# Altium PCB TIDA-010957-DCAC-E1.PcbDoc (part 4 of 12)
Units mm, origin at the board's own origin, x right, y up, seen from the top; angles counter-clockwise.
Board outline 300 x 300 mm, 4 copper layers (Top Layer, Layer 1, Layer 2, Bottom Layer), stack 1.787 mm thick; 1159 components, 619 nets, 3431 pads, 2942 vias.
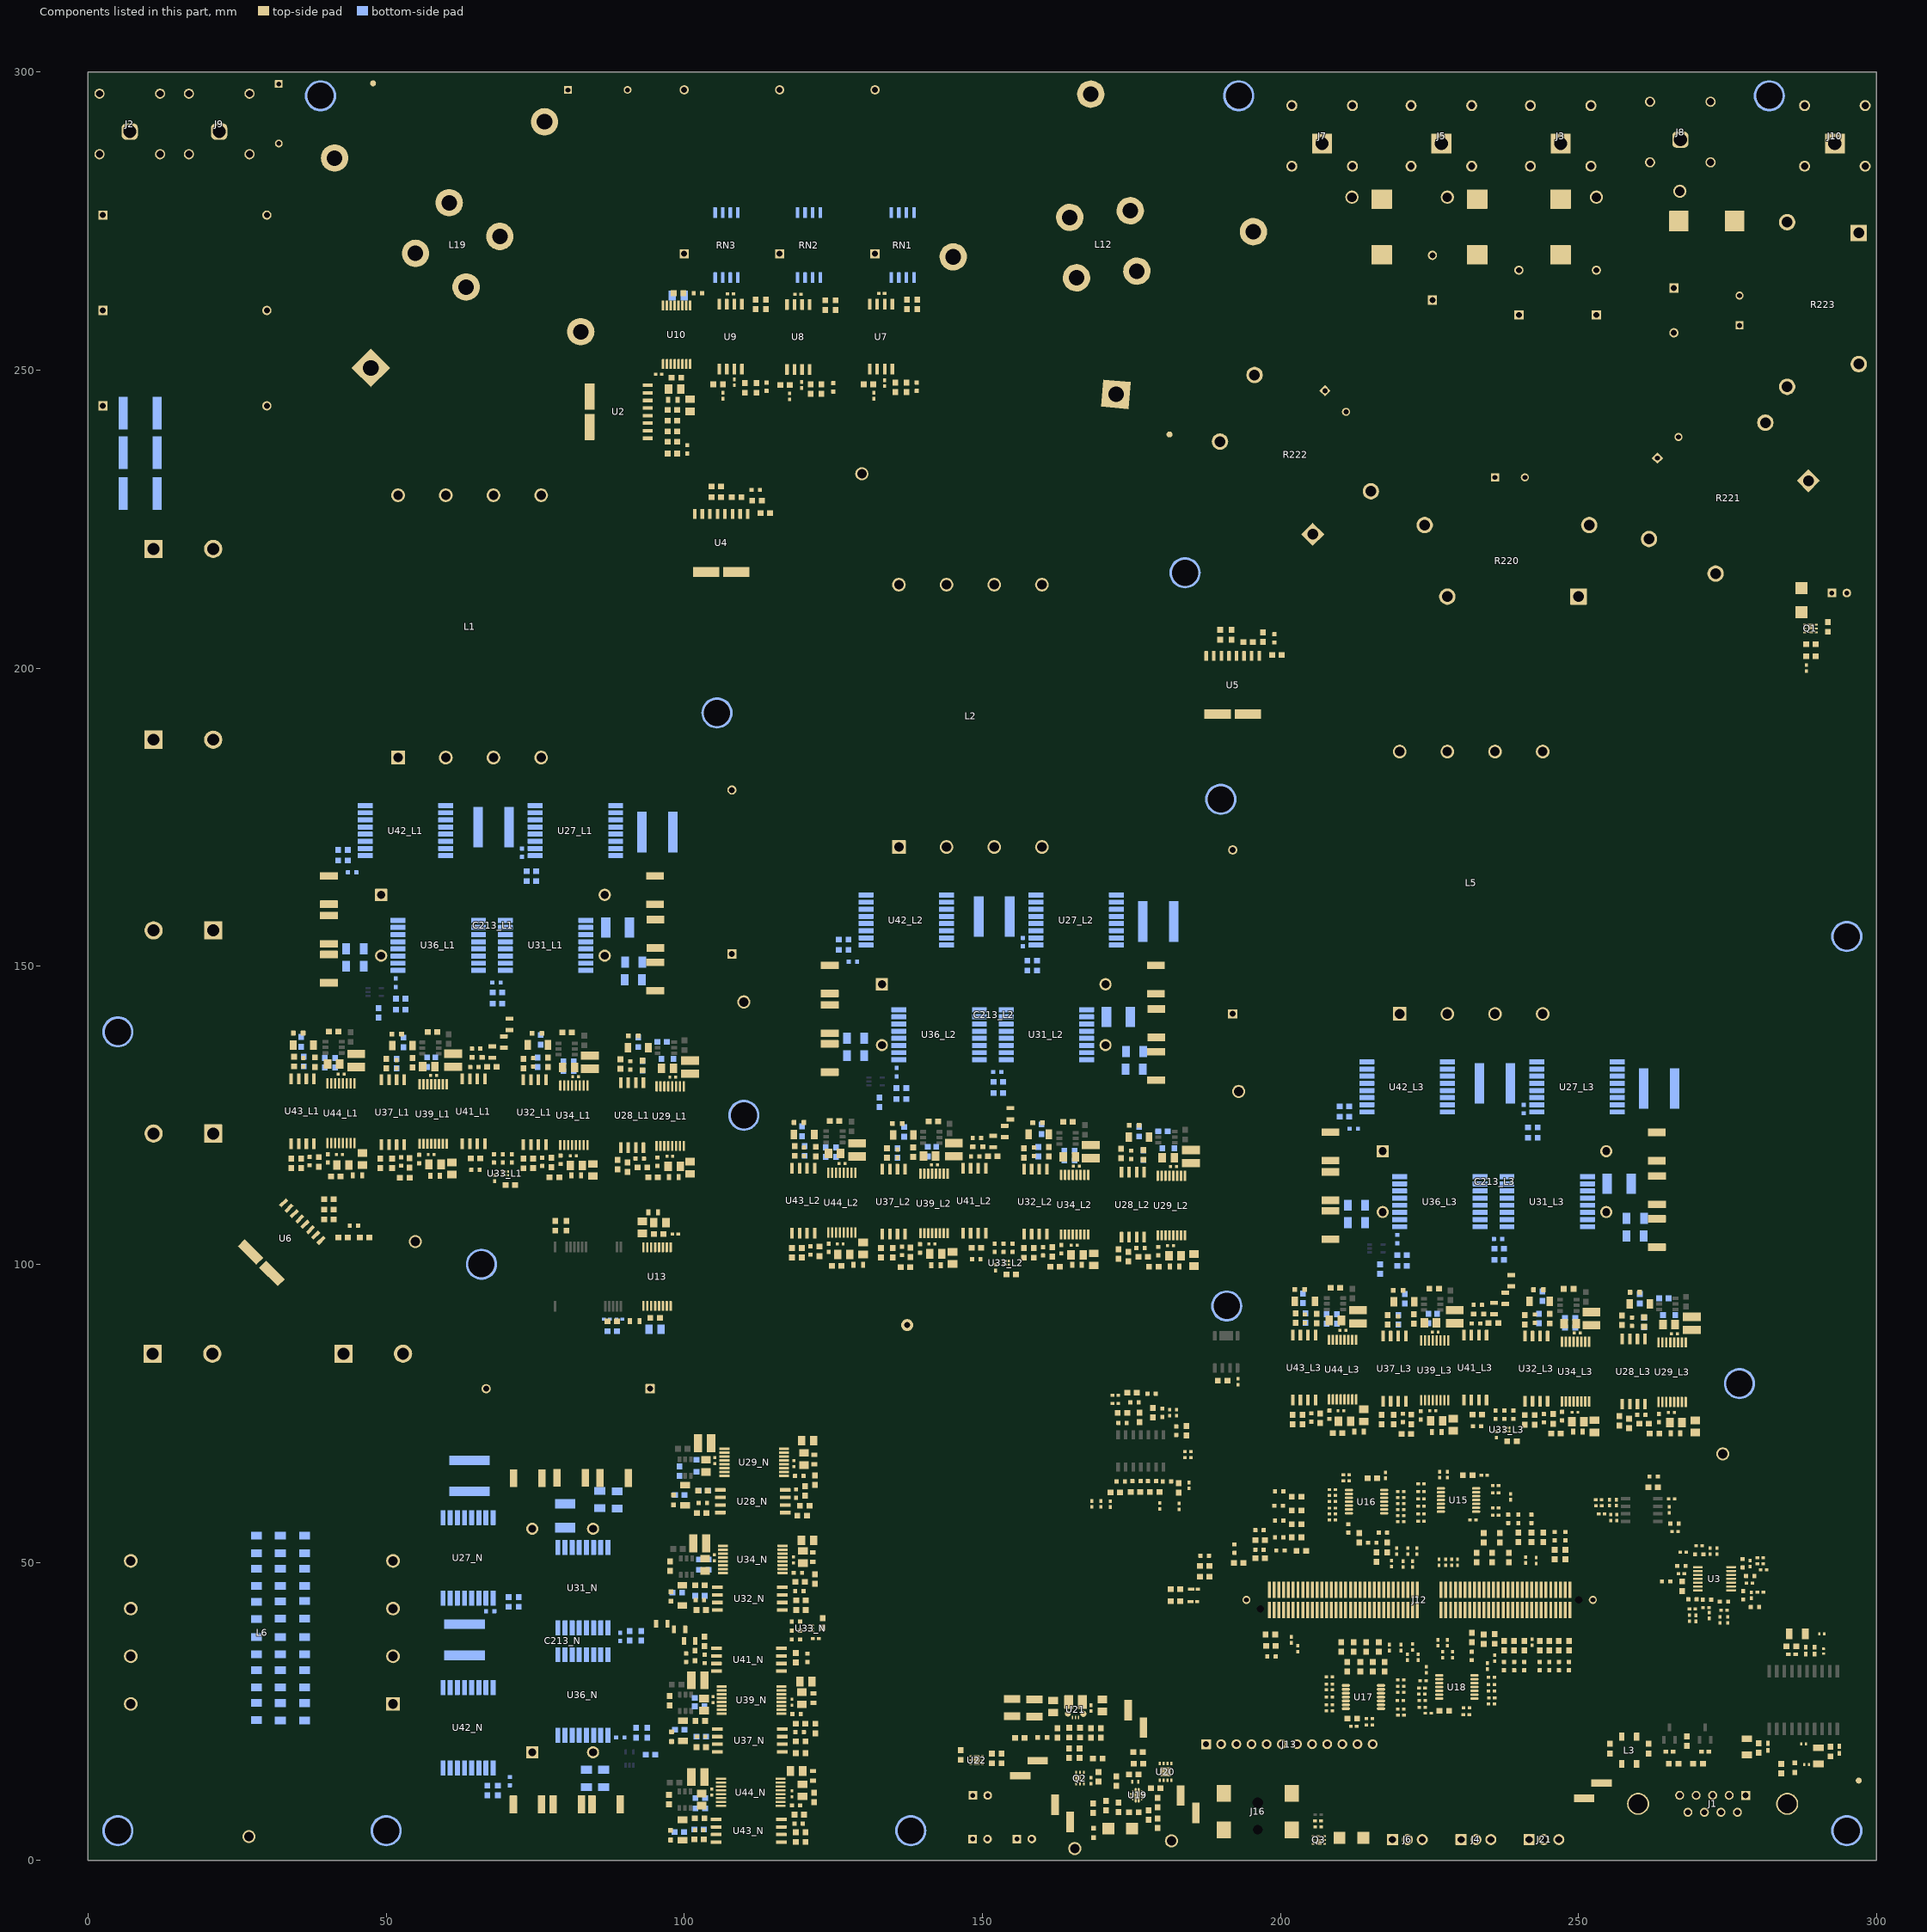
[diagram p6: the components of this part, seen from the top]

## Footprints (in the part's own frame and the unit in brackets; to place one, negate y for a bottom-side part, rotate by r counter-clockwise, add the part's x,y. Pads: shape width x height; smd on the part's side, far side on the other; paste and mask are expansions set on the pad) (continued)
DHA0016A-MFG [mm]
  rrect24% 1.65x0.41 smd paste+0 mask+0: 1(-4.925,2.275) 2(-4.925,1.625) 3(-4.925,0.975) 4(-4.925,0.325) 5(-4.925,-0.325) 6(-4.925,-0.975) 7(-4.925,-1.625) 8(-4.925,-2.275) 9(4.925,-2.275) 10(4.925,-1.625) 11(4.925,-0.975) 12(4.925,-0.325) 13(4.925,0.325) 14(4.925,0.975) 15(4.925,1.625) 16(4.925,2.275)
  silkscreen extent -6.42,-2.98 3.5,2.98, body extent -5.85,-3.22 5.85,3.22, height 0.25
DQK0006C [mm] "WSON"
  rrect12% 0.9x0.86 on Top Paste: 0(0,0.325)
  rrect34% 0.7x0.29 on Top Paste: 0(0.095,-0.65)
  rrect33% 0.45x0.3 smd: 1(-0.975,0.65) 2(-0.975,0) 3(-0.975,-0.65) 4(0.975,-0.65) 5(0.975,0) 6(0.975,0.65)
  rrect33% 0.75x0.3 smd paste-0.15: 7(0.095,-0.65)
  rrect11% 1x0.95 smd paste-0.5: 8(0,0.325)
  silkscreen extent -1.15,-1.15 1.15,1.15, body extent -1,-1 1,1, height 0.82
DRB0008A [mm] "VSON-8"
  rrect32% 0.6x0.31 smd: 1(-1.4,0.975) 2(-1.4,0.325) 3(-1.4,-0.325) 4(-1.4,-0.975) 5(1.4,-0.975) 6(1.4,-0.325) 7(1.4,0.325) 8(1.4,0.975)
  rrect7% 1.5x1.75 smd paste-0.75: 9(0,0)
  Top Layer region: -0.7,-0.875 -0.49,-0.875 -0.471,-0.879 -0.455,-0.89 -0.444,-0.906 -0.44,-0.925 -0.44,-0.925 -0.44,-1.65 -0.436,-1.669 -0.425,-1.685 -0.409,-1.696 -0.39,-1.7 -0.39,-1.7 -0.26,-1.7 -0.241,-1.696 -0.225,-1.685 -0.214,-1.669 -0.21,-1.65 -0.21,-1.65 -0.21,-0.925 -0.206,-0.906 -0.195,-0.89 -0.179,-0.879 -0.16,-0.875 -0.16,-0.875 0.16,-0.875 0.179,-0.879 0.195,-0.89 0.206,-0.906 0.21,-0.925 0.21,-0.925 0.21,-1.65 0.21,-1.65 0.214,-1.669 0.225,-1.685 0.241,-1.696 0.26,-1.7 0.26,-1.7 0.39,-1.7 0.409,-1.696 0.425,-1.685 0.436,-1.669 0.44,-1.65 0.44,-1.65 0.44,-0.925 0.444,-0.906 0.455,-0.89 0.471,-0.879 0.49,-0.875 0.49,-0.875 0.7,-0.875 0.719,-0.871 0.735,-0.86 0.746,-0.844 0.75,-0.825 0.75,-0.825 0.75,0.825 0.746,0.844 0.735,0.86 0.719,0.871 0.7,0.875 0.7,0.875 0.49,0.875 0.471,0.879 0.455,0.89 0.444,0.906 0.44,0.925 0.44,0.925 0.44,1.65 0.436,1.669 0.425,1.685 0.409,1.696 0.39,1.7 0.39,1.7 0.26,1.7 0.241,1.696 0.225,1.685 0.214,1.669 0.21,1.65 0.21,1.65 0.21,1.65 0.21,0.925 0.206,0.906 0.195,0.89 0.179,0.879 0.16,0.875 0.16,0.875 -0.16,0.875 -0.179,0.879 -0.195,0.89 -0.206,0.906 -0.21,0.925 -0.21,0.925 -0.21,1.65 -0.214,1.669 -0.225,1.685 -0.241,1.696 -0.26,1.7 -0.26,1.7 -0.39,1.7 -0.409,1.696 -0.425,1.685 -0.436,1.669 -0.44,1.65 -0.44,1.65 -0.44,0.925 -0.444,0.906 -0.455,0.89 -0.471,0.879 -0.49,0.875 -0.49,0.875 -0.7,0.875 -0.719,0.871 -0.735,0.86 -0.746,0.844 -0.75,0.825 -0.75,0.825 -0.75,-0.825 -0.746,-0.844 -0.735,-0.86 -0.719,-0.871 -0.7,-0.875
  silkscreen extent -1.73,-1.73 1.73,1.73, body extent -1.5,-1.5 1.5,1.5, height 0.77
DRV0006A [mm] "SON, 6-Leads, Body 2x2mm, Pitch 0.65mm, Thermal Pad 1.6x1mm, TI Recommended"
  rrect33% 0.45x0.3 smd: 1(-0.975,0.65) 2(-0.975,0) 3(-0.975,-0.65) 4(0.975,-0.65) 5(0.975,0) 6(0.975,0.65)
  rrect14% 1x0.7 on Top Paste: 7(0,-0.45) 7(0,0.45)
  rrect10% 1x1.6 smd paste-0.5: 7(0,0)
  silkscreen extent -1.05,-1.2 1.05,1.2, body extent -1.05,-1.05 1.05,1.05, height 0.81
DRY0006A [mm] "USON-6"
  rrect67% 0.45x0.3 smd paste-0.05 mask-0.05: 1(-0.275,0.5)
  rrect67% 0.4x0.3 smd paste-0.05 mask-0.05: 2(-0.3,0) 3(-0.3,-0.5) 4(0.3,-0.5) 5(0.3,0) 6(0.3,0.5)
  body extent -0.5,-0.72 0.5,0.72, height 0.58
DVG0010A-MFG [mm]
  rrect6% 1.65x4.41 smd paste+0 mask+0: 1(-4.875,2.54) 2(-4.875,-2.54)
  rrect17% 1.65x0.6 smd paste+0 mask+0: 3(4.875,-4.445) 4(4.875,-3.175) 5(4.875,-1.905) 6(4.875,-0.635) 7(4.875,0.635) 8(4.875,1.905) 9(4.875,3.175) 10(4.875,4.445)
  silkscreen extent -6.37,-5.25 3.67,5.25, body extent -5.15,-5.15 5.15,5.15, height 2.65
DWV0008A [mm] "SOIC, 8-Leads, Body 5.95x7.6mm (max), Pitch 1.27mm"
  rrect17% 1.8x0.6 smd: 1(-5.45,1.905) 2(-5.45,0.635) 3(-5.45,-0.635) 4(-5.45,-1.905) 5(5.45,-1.905) 6(5.45,-0.635) 7(5.45,0.635) 8(5.45,1.905)
  silkscreen extent -6.25,-2.95 2.98,2.95, body extent -5.77,-2.92 5.77,2.93, height 2.67
DWV0008A-MFG [mm]
  rrect17% 1.8x0.6 smd paste+0 mask+0: 1(-5.45,1.905) 2(-5.45,0.635) 3(-5.45,-0.635) 4(-5.45,-1.905) 5(5.45,-1.905) 6(5.45,-0.635) 7(5.45,0.635) 8(5.45,1.905)
  silkscreen extent -7.1,-2.98 3.8,2.98, body extent -5.75,-2.93 5.75,2.93, height 2.8
DWX0016A-MFG [mm]
  rrect24% 1.7x0.41 smd paste+0 mask+0: 1(-5,2.275) 2(-5,1.625) 3(-5,0.975) 4(-5,0.325) 5(-5,-0.325) 6(-5,-0.975) 7(-5,-1.625) 8(-5,-2.275) 9(5,-2.275) 10(5,-1.625) 11(5,-0.975) 12(5,-0.325) 13(5,0.325) 14(5,0.975) 15(5,1.625) 16(5,2.275)
  silkscreen extent -6.52,-2.98 3.8,2.98, body extent -5.16,-2.93 5.16,2.93, height 2.6
FCC_disclaimer [mm]
Fiducial10-20 [mm]
  round 1 smd mask+0.5: 1(0,0)
  Top Layer keep-out circle w1.178: c0,0 r0.5
FM_630x1120 [mm] "PANASONIC"
  rect 1.45x1.45 hole 0.787: 1(-1.25,0)
  round 1.45 hole 0.787: 2(1.25,0)
  silkscreen extent -3.4,-3.4 3.4,3.4, body extent -3.37,-3.39 3.4,3.39, height 12.71
FP-0022111031_HDR3-MFG [mm]
  rrect5% 1.85x1.85 hole 1.2 paste-2539.97 mask+0: 1(2.5,0.3)
  round 1.85 hole 1.2 paste-2539.97 mask+0: 2(0,0.3) 3(-2.5,0.3)
  silkscreen extent -4.1,-3.1 4.7,3.1, body extent -4.2,-3.2 4.2,3.2, height 0.25
FP-9774030960R_SPACER-MFG#1 [mm] "Recommended Land Pattern"
  round 5.245 smd paste-1000 mask-1000: 1(0,0)
  round 4.4 hole 4.4 unplated paste-2539.97 mask+0: ""(0,0)
  Top Layer circle w1.5: c0,0 r2.95
  silkscreen extent -4.08,-4.07 4.07,4.07, body extent -3,-3 2.99,3, height 3.1
FP-9774030960R_SPACER-MFG#2 [mm] "Recommended Land Pattern"
  round 5.245 smd paste-1000 mask-1000: 1(0,0)
  round 4.4 hole 4.4 unplated paste-2539.97 mask+0: ""(0,0)
  Top Layer lines w1.5: 2.615,1.365 cw(c0,0) -2.95,0 cw(c0,0) 2.615,1.365
  silkscreen extent -4.08,-4.07 4.07,4.07, body extent -3,-3 2.99,3, height 3.1
FP-ACT45B-101-2P-TL003_SMT_4MM5_3MM2-MFG [mm]
  rrect11% 1.35x0.9 smd paste+0 mask+0: 1(-2.275,1.25) 2(-2.275,-1.25) 3(2.275,-1.25) 4(2.275,1.25)
  silkscreen extent -3.62,-1.7 2.35,1.7, body extent -3.05,-1.8 3.05,1.8, height 0.25
FP-ALA7DA301CF550_RADIAL-MFG [mm] "Recommended Land Pattern"
  rrect3% 3.05x3.05 hole 2 paste-2539.97 mask+0: 1(-5,0)
  round 3.05 hole 2 paste-2539.97 mask+0: 2(5,0)
  silkscreen extent -15.5,-15.5 15.5,15.5, body extent -15.6,-15.6 15.6,15.6, height 0.25
FP-APG1608SURKC_T_0603-MFG [mm]
  rrect13% 0.8x0.8 smd paste-1000 mask+0: 1(-0.825,0) 2(0.825,0)
  silkscreen extent -1.92,-0.8 0.85,0.8, body extent -1.33,-0.55 1.33,0.55, height 0.25
FP-B32676G6126K000_RADIAL-MFG [mm] "Recommended Land Pattern"
  round 2.05 hole 1.35 paste-2539.97 mask+0: 1(-18.75,-5.1) 2(18.75,-5.1) 2(18.75,5.1)
  rrect5% 2.05x2.05 hole 1.35 paste-2539.97 mask+0: 1(-18.75,5.1)
  silkscreen extent -21,-14 21,14, body extent -21.1,-14.1 21.1,14.1, height 0.25
FP-B32774X1305K000_RADIAL-MFG [mm] "Recommended Land Pattern"
  rrect6% 1.55x1.55 hole 1 paste-2539.97 mask+0: 1(-13.75,0)
  round 1.55 hole 1 paste-2539.97 mask+0: 2(13.75,0)
  silkscreen extent -15.75,-9 15.75,9, body extent -15.85,-9.1 15.85,9.1, height 0.25
FP-B58043E5254M052_2220-MFG [mm]
  rrect7% 1.5x5.5 smd paste+0 mask+0: 1(-2.85,0) 2(2.85,0)
  silkscreen extent -1.73,-2.7 1.73,2.7, body extent -2.85,-2.5 2.85,2.5, height 1.6
"FP-B181178 V0 D6937_PTH8-MFG" [mm] "Recommended Land Pattern"
  rrect2% 4.6x4.6 hole 2.6 paste-2539.97 mask+0: 1(-4.3,24.9)
  round 4.6 hole 2.6 paste-2539.97 mask+0: 2(-6,4) 3(-24.9,-4.3) 4(-4,-6) 5(4.3,-24.9) 6(6,-4) 7(24.9,4.3) 8(4,6)
  silkscreen extent -28.37,-28.37 28.37,28.37, body extent -28.35,-28.35 28.35,28.35, height 0.25
"FP-B181179 V0 D6938_PTH8-MFG" [mm] "Recommended Land Pattern"
  rrect4% 2.3x2.3 hole 1.6 paste-2539.97 mask+0: 1(-22,12)
  round 2.3 hole 1.6 paste-2539.97 mask+0: 2(-22,4) 3(-22,-4) 4(-22,-12) 5(22,-12) 6(22,-4) 7(22,4) 8(22,12)
  silkscreen extent -29.17,-29.75 28.45,29.75, body extent -28.55,-29.85 28.55,29.85, height 0.25
FP-BLM15EX331SN1D_0402-MFG [mm]
  rrect25% 0.4x0.5 smd paste+0 mask+0: 1(-0.4,0) 2(0.4,0)
  silkscreen extent -0.53,-0.63 0.52,0.63, body extent -0.7,-0.38 0.7,0.38, height 0.25
FP-CGA3E2C0G1H331J080AA_0603-MFG [mm]
  rrect14% 0.7x0.7 smd paste+0 mask+0: 1(-0.7,0) 2(0.7,0)
  silkscreen extent -0.95,-0.72 0.95,0.72, body extent -1.15,-0.65 1.15,0.65, height 0.25
FP-FCR7350G_CONN_BANANA_JACK-MFG [mm]
  rrect3% 3.35x3.35 hole 2.2 paste-2539.97 mask+0: 1(11,0)
  round 1.85 hole 1.2 paste-2539.97 mask+0: 2(4.64,5.08) 3(14.8,5.08) 4(4.64,-5.08) 5(14.8,-5.08)
  silkscreen extent -1.83,-6.05 17.2,6.05, body extent -16.7,-6.15 16.7,6.15, height 0.25
FP-FCR7350N_CONN_BANANA_JACK-MFG [mm]
  rrect3% 3.35x3.35 hole 2.2 paste-2539.97 mask+0: 1(11,0)
  round 1.85 hole 1.2 paste-2539.97 mask+0: 2(4.64,5.08) 3(14.8,5.08) 4(4.64,-5.08) 5(14.8,-5.08)
  silkscreen extent -1.83,-6.05 17.2,6.05, body extent -16.7,-6.15 16.7,6.15, height 0.25
FP-FTR-K3AB012W-WG_PTH_RELAY_30MM1_15MM7-MFG [mm] "Recommended Land Pattern"
  rrect4% 2.75x2.75 hole 1.8 paste-2539.97 mask+0: 1(-12,5.75)
  round 2.75 hole 1.8 paste-2539.97 mask+0: 2(10,5.75) 3(13.8,-6.25) 4(-13.8,-6.25)
  silkscreen extent -15.88,-8 15.2,8, body extent -15.3,-8.1 15.3,8.1, height 0.25
FP-IsoM5-275-B-L2_RADIAL-MFG [mm]
  rrect6% 1.55x1.55 hole 1 paste-2539.97 mask+0: 1(-3.75,0)
  round 1.55 hole 1 paste-2539.97 mask+0: 2(3.75,0)
  silkscreen extent -8.5,-3.15 8.5,3.15, body extent -8.6,-3.25 8.6,3.25, height 0.25
"FP-KG DELLS1.22-JGKH-24_0603-MFG" [mm]
  rrect20% 1.05x0.5 smd paste-1000 mask+0: 1(-0.47,0)
  rrect20% 0.7x0.5 smd paste-1000 mask+0: 2(0.645,0)
  silkscreen extent -1.67,-0.63 0.75,0.63, body extent -1.09,-0.55 1.09,0.55, height 0.25
FP-MH1608-601Y_0603-MFG [mm]
  rrect14% 0.7x0.7 smd paste+0 mask+0: 1(-0.7,0) 2(0.7,0)
  silkscreen extent -0.87,-0.8 0.87,0.8, body extent -0.8,-0.4 0.8,0.4, height 1
FP-PTCEL13R600LBE_RADIAL-MFG [mm]
  rrect7% 1.35x1.35 hole 0.85 paste-2539.97 mask+0: 1(-2.5,0)
  round 1.35 hole 0.85 paste-2539.97 mask+0: 2(2.5,0)
  silkscreen extent -6.75,-3.5 6.75,3.5, body extent -6.85,-3.6 6.85,3.6, height 0.25
FP-R413F147050T1K_RADIAL-MFG [mm]
  rrect8% 1.3x1.3 hole 0.8 paste-2539.97 mask+0: 1(-5,0)
  round 1.3 hole 0.8 paste-2539.97 mask+0: 2(5,0)
  silkscreen extent -6.65,-2.6 6.65,2.6, body extent -6.75,-2.7 6.75,2.7, height 0.25
FP-R523R447050P1M_RADIAL-MFG [mm]
  rrect6% 1.55x1.55 hole 1 paste-2539.97 mask+0: 1(-13.75,0)
  round 1.55 hole 1 paste-2539.97 mask+0: 2(13.75,0)
  silkscreen extent -16.15,-7.1 16.15,7.1, body extent -16.25,-7.2 16.25,7.2, height 0.25
FP-RT0603BRE078KL_0603-MFG [mm]
  rrect13% 0.9x0.8 smd paste+0 mask+0: 1(-0.85,0) 2(0.85,0)
  silkscreen extent -0.85,-0.81 0.86,0.8, body extent -0.8,-0.4 0.8,0.4, height 0.55
FP-SF-3812F2500T-2_SMD2-MFG [mm]
  rrect3% 3.25x3.43 smd paste+0 mask+0: 1(-4.675,0) 2(4.675,0)
  silkscreen extent -2.68,-1.65 2.68,1.65, body extent -6.4,-1.82 6.4,1.82, height 0.25
FP-TNPV0805680KBEEA_0805-MFG [mm] "Recommended Land Pattern"
  rrect14% 0.7x1.3 smd paste+0 mask+0: 1(-0.95,0) 2(0.95,0)
  silkscreen extent -0.23,-0.7 0.23,0.7, body extent -1,-0.63 1,0.63, height 0.55
FP-ZGL41-180A-E3/96_GL41-MFG [mm]
  rrect8% 1.25x3 smd paste+0 mask+0: 1(-2.375,0) 2(2.375,0)
  silkscreen extent -3.67,-1.34 1.38,1.34, body extent -3.1,-1.6 3.1,1.6, height 0.25
Keystone5001 [mil] "For Keystone 500x miniature loop terminals"
  round 80 hole 40: 1(0,0)
  silkscreen extent -52,-52 52,52, body extent -49,-49 49,49, height 182
Keystone5010 [mil] "Keystone Multipurpose loops"
  round 87 hole 63: 1(0,0)
  silkscreen extent -70,-70 70,70, body extent -63,-63 63,62, height 319
Keystone5011 [mil] "Keystone Multipurpose loops"
  round 87 hole 63: 1(0,0)
  silkscreen extent -70,-70 70,70, body extent -63,-63 63,62, height 319
KLF0016A-MFG [mm]
  rrect12% 2.5x0.85 smd paste+0 mask+0: 1(-6.75,4.2) 2(-6.75,3) 3(-6.75,1.8) 4(-6.75,0.6) 5(-6.75,-0.6) 6(-6.75,-1.8) 7(-6.75,-3) 8(-6.75,-4.2) 9(6.75,-4.2) 10(6.75,-3) 11(6.75,-1.8) 12(6.75,-0.6) 13(6.75,0.6) 14(6.75,1.8) 15(6.75,3) 16(6.75,4.2)
  silkscreen extent -8.68,-4.97 5.1,4.97, body extent -7.5,-4.95 7.5,4.95, height 2.35
Label_650x200 [mil] "Thermal Transfer Label"
  round 1 on Mech13: 0(0,0)
  silkscreen extent -325,-100 325,100, body extent -325,-100 325,100, height 1
PW0014A-MFG [mm]
  rrect29% 1.6x0.35 smd paste-1000 mask+0: 1(-2.8,1.95) 2(-2.8,1.3) 3(-2.8,0.65) 4(-2.8,0) 5(-2.8,-0.65) 6(-2.8,-1.3) 7(-2.8,-1.95) 8(2.8,-1.95) 9(2.8,-1.3) 10(2.8,-0.65) 11(2.8,0) 12(2.8,0.65) 13(2.8,1.3) 14(2.8,1.95)
  silkscreen extent -4.32,-2.55 2.25,2.55, body extent -3.7,-2.8 3.7,2.8, height 0.25
PW0014A_N [mm] "TSOP, 14-Leads, Body 5x4.4mm, Pitch 0.65mm, IPC Medium Density"
  oval 1.4x0.45 smd: 1(-2.95,1.95) 2(-2.95,1.3) 3(-2.95,0.65) 4(-2.95,0) 5(-2.95,-0.65) 6(-2.95,-1.3) 7(-2.95,-1.95) 8(2.95,-1.95) 9(2.95,-1.3) 10(2.95,-0.65) 11(2.95,0) 12(2.95,0.65) 13(2.95,1.3) 14(2.95,1.95)
  silkscreen extent -3.4,-2.55 1.85,2.55, body extent -3.21,-2.5 3.21,2.5, height 1
RDX0007A-MFG [mm]
  round 1.025 smd paste-1000 mask-1000: 1(-1.312,1.312)
  rrect13% 1.5x2.3 smd paste-1000 mask-1000: 2(-1.15,-0.675) 3(1.15,-0.675)
  round 0.991 smd paste-1000 mask-1000: 4(1.281,1.276)
  rrect45% 0.22x0.6 smd paste+0 mask-1000: 5(0.5,1.9) 6(0,1.9) 7(-0.5,1.9)
  Top Layer region: -1.9,1.8 -1.887,1.85 -1.85,1.887 -1.8,1.9 -1.8,1.9 -0.925,1.9 -0.887,1.892 -0.854,1.871 -0.833,1.838 -0.825,1.8 -0.825,1.8 -0.825,1.634 -0.818,1.596 -0.796,1.563 -0.796,1.563 -0.507,1.274 -0.474,1.252 -0.436,1.245 -0.436,1.245 -0.39,1.245 -0.34,1.232 -0.303,1.195 -0.29,1.145 -0.29,1.145 -0.29,0.825 -0.298,0.787 -0.319,0.754 -0.352,0.733 -0.39,0.725 -0.39,0.725 -1.8,0.725 -1.838,0.733 -1.871,0.754 -1.892,0.787 -1.9,0.825 -1.9,0.825
  Top Layer region: 1.9,1.8 1.892,1.838 1.871,1.871 1.838,1.892 1.8,1.9 1.8,1.9 0.925,1.9 0.887,1.892 0.854,1.871 0.833,1.838 0.825,1.8 0.825,1.8 0.825,1.634 0.818,1.596 0.796,1.563 0.796,1.563 0.507,1.274 0.474,1.252 0.436,1.245 0.436,1.245 0.39,1.245 0.352,1.237 0.319,1.216 0.298,1.183 0.29,1.145 0.29,1.145 0.29,0.825 0.298,0.787 0.319,0.754 0.352,0.733 0.39,0.725 0.39,0.725 1.8,0.725 1.838,0.733 1.871,0.754 1.892,0.787 1.9,0.825 1.9,0.825
  Top Layer keep-out region: -0.2,0.675 0.2,0.675 0.2,1.295 -0.2,1.295
  silkscreen extent -2.53,-2.17 2.07,2.37, body extent -2,-2.1 2,2.3, height 0.25
RPW0010A-MFG [mm]
  round 0.27 smd paste-1000 mask+0: 1(-0.75,0.7) 10(0.75,0.7)
  rrect40% 0.6x0.25 smd paste+0 mask+0: 2(-0.9,0.225) 3(-0.9,-0.225) 8(0.9,-0.225) 9(0.9,0.225)
  round 0.255 smd paste-1000 mask+0: 4(-0.75,-0.75) 7(0.75,-0.75)
  rrect33% 0.3x2.4 smd paste-1000 mask+0: 5(-0.25,0) 6(0.25,0)
  Top Layer region: 0.85,0.85 0.85,1.15 0.846,1.169 0.835,1.185 0.819,1.196 0.8,1.2 0.8,1.2 0.65,1.2 0.631,1.196 0.615,1.185 0.604,1.169 0.6,1.15 0.6,1.15 0.6,0.6 0.604,0.581 0.615,0.565 0.631,0.554 0.65,0.55 0.65,0.55 1.15,0.55 1.169,0.554 1.185,0.565 1.196,0.581 1.2,0.6 1.2,0.6 1.2,0.8 1.196,0.819 1.185,0.835 1.169,0.846 1.15,0.85 1.15,0.85
  Top Layer region: 0.85,-0.85 0.85,-1.15 0.846,-1.169 0.835,-1.185 0.819,-1.196 0.8,-1.2 0.8,-1.2 0.65,-1.2 0.631,-1.196 0.615,-1.185 0.604,-1.169 0.6,-1.15 0.6,-1.15 0.6,-0.6 0.604,-0.581 0.615,-0.565 0.631,-0.554 0.65,-0.55 0.65,-0.55 1.15,-0.55 1.169,-0.554 1.185,-0.565 1.196,-0.581 1.2,-0.6 1.2,-0.6 1.2,-0.8 1.196,-0.819 1.185,-0.835 1.169,-0.846 1.15,-0.85 1.15,-0.85
  Top Layer region: -0.85,-0.85 -0.85,-1.15 -0.846,-1.169 -0.835,-1.185 -0.819,-1.196 -0.8,-1.2 -0.8,-1.2 -0.65,-1.2 -0.631,-1.196 -0.615,-1.185 -0.604,-1.169 -0.6,-1.15 -0.6,-1.15 -0.6,-0.6 -0.604,-0.581 -0.615,-0.565 -0.631,-0.554 -0.65,-0.55 -0.65,-0.55 -1.15,-0.55 -1.169,-0.554 -1.185,-0.565 -1.196,-0.581 -1.2,-0.6 -1.2,-0.6 -1.2,-0.8 -1.196,-0.819 -1.185,-0.835 -1.169,-0.846 -1.15,-0.85 -1.15,-0.85
  Top Layer region: -0.85,0.85 -0.85,1.15 -0.843,1.175 -0.825,1.193 -0.8,1.2 -0.8,1.2 -0.65,1.2 -0.631,1.196 -0.615,1.185 -0.604,1.169 -0.6,1.15 -0.6,1.15 -0.6,0.6 -0.604,0.581 -0.615,0.565 -0.631,0.554 -0.65,0.55 -0.65,0.55 -1.15,0.55 -1.169,0.554 -1.185,0.565 -1.196,0.581 -1.2,0.6 -1.2,0.6 -1.2,0.8 -1.193,0.825 -1.175,0.843 -1.15,0.85 -1.15,0.85
  silkscreen extent -1.88,-1.58 1.05,1.58, body extent -1.3,-1.3 1.3,1.3, height 0.25
Samtec_TSM-102-01-T-SV-P-TR [mil] "SMD, 2-Leads, Body 200x100mil"
  rect 50x135 smd: 1(-50,57.5) 2(50,-57.5)
  silkscreen extent -100,-50 100,92, body extent -100,-96 100,96, height 380
SDR0302 [mm] "BOURNS"
  rect 1.4x3 smd: 1(-1.1,0) 2(1.1,0)
  body extent -1.65,-1.65 1.65,1.65, height 2.8
SMA [mm] "Molded Diode, 2-Leads, Body 4.3x2.6mm, IPC Medium Density, based on OnSemi component dimensions and land pattern"
  rect 2x2 smd: 1(-2,0) 2(2,0)
  silkscreen extent -3.66,-1.57 2.79,1.57, body extent -2.6,-1.3 2.6,1.3, height 2.42
TI_Stacked_Overlay_Small [mm]
  silkscreen extent -10.63,-2.49 10.63,2.49
TSW-112-07-G-S [mm] "Samtec 100mil, 1x12, 230 mil above insulator"
  rrect6% 1.65x1.65 hole 1.016 mask+0: 1(-13.97,0)
  round 1.65 hole 1.016 mask+0: 2(-11.43,0) 3(-8.89,0) 4(-6.35,0) 5(-3.81,0) 6(-1.27,0) 7(1.27,0) 8(3.81,0) 9(6.35,0) 10(8.89,0) 11(11.43,0) 12(13.97,0)
  silkscreen extent -15.24,-1.27 15.24,1.65, body extent -15.24,-1.27 15.24,1.27, height 8.38
WCAP-CSGP_0402_L1W0.5H0.5 [mm] "Ceramic Capacitors, body 1x0.5mm"
  rect 0.5x0.5 smd: 1(-0.5,0) 2(0.5,0)
  body extent -0.5,-0.25 0.5,0.25, height 0.5
WE-PMI_0603_L1.6W0.8H0.8 [mm] "Power Multilayer Inductor, body 1.6x0.8mm"
  rect 0.7x1 smd: 1(-0.8,0) 2(0.8,0)
  body extent -0.8,-0.4 0.8,0.4, height 0.8
WEEE_Minimum [mm] "WEEElie bin"
  silkscreen extent -2.42,-4.38 2.52,2.65
WL-SMCW_GREEN [mm] "WURTH"
  rect 0.8x0.8 smd: 1(-0.8,0) 2(0.8,0)
  silkscreen extent -1.9,-0.8 1.2,0.8, body extent -0.85,-0.45 0.85,0.45, height 0.8
Wurth_618009231121 [mm] "Receptacle, D-Sub, 9 Position, R/A, TH"
  rect 1.5x1.5 hole 1: 1(-10.92,5.54)
  round 1.5 hole 1: 2(-10.92,2.77) 3(-10.92,0) 4(-10.92,-2.77) 5(-10.92,-5.54) 6(-8.08,4.155) 7(-8.08,1.385) 8(-8.08,-1.385) 9(-8.08,-4.155)
  round 3.7 hole 3.2: 10(-9.5,12.5) 11(-9.5,-12.5)
  silkscreen extent -12.78,-15.4 -0.53,15.4, body extent -12.5,-15.4 6,15.4, height 12.5

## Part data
C1 C2 C3 C7 C8 C9: library part CMP-0124364-1, "300 µF 550 V Aluminum Electrolytic Capacitors Radial, Can - Snap-In 567mOhm @ 100Hz 13000 Hrs @ 85°C", Digikey Part Number=399-ALA7DA301CF550-ND, Leakage Current=990uA, Manufacturer=KEMET, Mouser Part Number=80-ALA7DA301CF550, Operating Temperature Range="-40°C to +85°C", Tolerance_%=20%, ValueDisplayed=300uF
C4 C26 C259 C260: library part CMP-0010339-1, "CAP, AL, 100 uF, 25 V, +/- 20%, 0.13 ohm, TH", Cap_Case=6.3x11.2, Manufacturer=Panasonic, Supplier Part Number 1=P12924-ND, Tolerance_%=20%, Value1="0.13 ohm", Value2=25V, ValueDisplayed=100uF
C5 C14 C29 C31 C32 C33 C35 C37 C38 C39 C41 C43 C44 C45 C48 C50 C51 C52 C59 C66 C73 C84 C95 C96 C97 C98 C99 C100 C101 C102 C103 C104 C105 C106 C159 C160 C161 C162 C188_L1 C188_L2 C188_L3 C188_N C189_L1 C189_L2 C189_L3 C189_N C191_L1 C191_L2 C191_L3 C191_N C196_L1 C196_L2 C196_L3 C196_N C202_L1 C202_L2 C202_L3 C202_N C203_L1 C203_L2 C203_L3 C203_N C205_L1 C205_L2 C205_L3 C205_N C206_L1 C206_L2 C206_L3 C206_N C207_L1 C207_L2 C207_L3 C207_N C209_L1 C209_L2 C209_L3 C209_N C219_L1 C219_L2 C219_L3 C219_N C226_L1 C226_L2 C226_L3 C226_N C227_L1 C227_L2 C227_L3 C227_N C230_L1 C230_L2 C230_L3 C230_N C231_L1 C231_L2 C231_L3 C231_N C236_L1 C236_L2 C236_L3 C236_N C242_L1 C242_L2 C242_L3 C242_N C245_L1 C245_L2 C245_L3 C245_N C246_L1 C246_L2 C246_L3 C246_N C248_L1 C248_L2 C248_L3 C248_N C253_L1 C253_L2 C253_L3 C253_N C262: library part CMP-0095085-1, "Cap Ceramic 330pF 50V C0G 5% Pad SMD 0603 +125°C Automotive T/R", Manufacturer=TDK, Operating Temperature Range="-55°C to +125°C", TempCo=30ppm/°C, Temperature Characteristic=C0G, Tolerance_%=0.05%, ValueDisplayed=330pF
C6 C151 C155: library part CMP-0008802-2, "CAP, CERM, 10 uF, 50 V, +/- 10%, X7R, 1206", Cap_Case=1206, Manufacturer=Samsung, Supplier Part Number 1=1276-6767-1-ND, TempCo=X7R, Tolerance_%=10%, Value1=Unknown, Value2=50V, ValueDisplayed=10uF
C10 C11 C12: library part CMP-0124365-1, "3 µF Film Capacitor 1200V (1.2kV) Polypropylene (PP), Metallized Radial", Digikey Part Number=495-B32774X1305K000-ND, Manufacturer=TDK, Mouser Part Number=871-B32774X1305K000, Operating Temperature Range="-40°C to +105°C", Tolerance_%=10%, ValueDisplayed=3uF
C13 C16 C27 C28 C30 C34 C36 C40 C42 C46 C47 C49 C53 C55 C56 C60 C62 C63 C67 C69 C70 C74 C76 C77 C81 C82 C88 C90 C91 C94 C107 C113 C114 C125 C138 C186_L1 C186_L2 C186_L3 C186_N C187_L1 C187_L2 C187_L3 C187_N C190_L1 C190_L2 C190_L3 C190_N C195_L1 C195_L2 C195_L3 C195_N C200_L1 C200_L2 C200_L3 C200_N C201_L1 C201_L2 C201_L3 C201_N C204_L1 C204_L2 C204_L3 C204_N C212_L1 C212_L2 C212_L3 C212_N C223_L1 C223_L2 C223_L3 C223_N C224_L1 C224_L2 C224_L3 C224_N C225_L1 C225_L2 C225_L3 C225_N C228_L1 C228_L2 C228_L3 C228_N C229_L1 C229_L2 C229_L3 C229_N C235_L1 C235_L2 C235_L3 C235_N C240_L1 C240_L2 C240_L3 C240_N C241_L1 C241_L2 C241_L3 C241_N C243_L1 C243_L2 C243_L3 C243_N C244_L1 C244_L2 C244_L3 C244_N C247_L1 C247_L2 C247_L3 C247_N C252_L1 C252_L2 C252_L3 C252_N: library part CMP-0006752-5, "CAP, CERM, 0.1 uF, 25 V, +/- 5%, X7R, 0603", Cap_Case=0603, Manufacturer=AVX, Supplier Part Number 1=478-3713-1-ND, TempCo=X7R, Tolerance_%=5%, Value1="0.05 ohm", Value2=25V, ValueDisplayed=0.1uF
C15: library part CMP-0086152-1, "CAP, CERM, 1 µF, 25 V,+/- 10%, X5R, 0603", Cap_Case=0603, Manufacturer="Taiyo Yuden", TempCo=X5R, Tolerance_%=10%, Value2=25V, ValueDisplayed=1µF
C17 C18 C19 C20 C21 C22: library part CMP-0098409-1, "4.7 µF Film Capacitor 310V 630V Polypropylene (PP), Metallized Radial", Digikey Part Number=399-R523R447050P1M-ND, Manufacturer=KEMET, Mouser Part Number=80-R523R447050P1M, Operating Temperature Range="-40°C to +110°C", Tolerance_%=20%, ValueDisplayed=4.7uF, Voltage Ac Rating X=310V
C23 C257 C258: library part CMP-0098327-1, "0.25 µF ±20% 500V Ceramic Capacitor 2220 (5750 Metric)", Digikey Part Number=495-B58043E5254M052CT-ND, Manufacturer=TDK, Mouser Part Number=871-B58043E5254M052, Operating Temperature Range="-40°C to +150°C", Tolerance_%=20%, ValueDisplayed=250nF
C24 C25: library part CMP-0098408-1, "Cap Film 0.0047uF 1500V PP 10% Dipped 10mm 125°C Bulk", Digikey Part Number=399-R413F147050T1K-ND, Manufacturer=KEMET, Mouser Part Number=80-R413F147050T1K, Operating Temperature Range="-40°C to +125°C", Tolerance_%=10%, ValueDisplayed=4700pF, Voltage Ac Rating Y=300V
C54 C57 C61 C64 C68 C71 C80 C87 C144 C145: library part CMP-0007121-4, "CAP, CERM, 2.2 uF, 16 V, +/- 10%, X7R, 0603", Cap_Case=0603, Manufacturer="Taiyo Yuden", Supplier Part Number 1=EMK107BB7225KA-T-ND, TempCo=X7R, Tolerance_%=10%, Value1=Unknown, Value2=16V, ValueDisplayed=2.2uF
C58 C65 C72 C83 C86 C263: library part CMP-0006309-2, "CAP, CERM, 1000 pF, 50 V, +/- 5%, C0G/NP0, AEC-Q200 Grade 1, 0402", Cap_Case=0402, Manufacturer=TDK, Supplier Part Number 1=445-6885-1-ND, TempCo=C0G/NP0, Tolerance_%=5%, Value1=Unknown, Value2=50V, ValueDisplayed=1000pF
C75 C78 C79 C89 C92 C93 C143 C194_L1 C194_L2 C194_L3 C194_N C197_L1 C197_L2 C197_L3 C197_N C198_L1 C198_L2 C198_L3 C198_N C211_L1 C211_L2 C211_L3 C211_N C220_L1 C220_L2 C220_L3 C220_N C221_L1 C221_L2 C221_L3 C221_N C234_L1 C234_L2 C234_L3 C234_N C237_L1 C237_L2 C237_L3 C237_N C238_L1 C238_L2 C238_L3 C238_N C251_L1 C251_L2 C251_L3 C251_N C254_L1 C254_L2 C254_L3 C254_N C255_L1 C255_L2 C255_L3 C255_N: library part CMP-0008377-2, "CAP, CERM, 22 uF, 10 V, +/- 20%, X7R, 0805", Cap_Case=0805, Manufacturer=MuRata, Supplier Part Number 1=81-GRM21BZ71A226ME5L, TempCo=X7R, Tolerance_%=20%, Value1=Unknown, Value2=10V, ValueDisplayed=22uF
C85: library part CMP-0006673-2, "CAP, CERM, 1000 pF, 50 V, +/- 10%, X7R, 0402", Cap_Case=0402, Manufacturer=MuRata, Supplier Part Number 1=490-1303-1-ND, TempCo=X7R, Tolerance_%=10%, Value1=Unknown, Value2=50V, ValueDisplayed=1000pF
C108 C109 C110 C111 C112 C115 C116 C117 C118 C119 C120 C121 C122 C123 C124 C126 C127 C128 C129 C130: library part CMP-0006410-2, "CAP, CERM, 100 pF, 50 V, +/- 5%, C0G/NP0, 0402", Cap_Case=0402, Manufacturer=MuRata, Supplier Part Number 1=81-GRM1555C1H101JA1D, TempCo=C0G/NP0, Tolerance_%=5%, Value1=Unknown, Value2=50V, ValueDisplayed=100pF
C131 C133: library part CMP-0007052-4, "CAP, CERM, 1 uF, 35 V, +/- 10%, X7R, 0603", Cap_Case=0603, Manufacturer=TDK, Supplier Part Number 1=445-7414-1-ND, TempCo=X7R, Tolerance_%=10%, Value1=Unknown, Value2=35V, ValueDisplayed=1uF
C132 C142: library part CMP-0006356-2, "CAP, CERM, 0.1 uF, 50 V, +/- 10%, X7R, AEC-Q200 Grade 1, 0402", Cap_Case=0402, Manufacturer=MuRata, Supplier Part Number 1=490-10672-1-ND, TempCo=X7R, Tolerance_%=10%, Value1=Unknown, Value2=50V, ValueDisplayed=0.1uF
C134: library part CMP-0007477-4, "CAP, CERM, 2700 pF, 100 V, +/- 10%, X7R, 0603", Cap_Case=0603, Manufacturer=MuRata, Supplier Part Number 1=490-1480-1-ND, TempCo=X7R, Tolerance_%=10%, Value1=Unknown, Value2=100V, ValueDisplayed=2700pF
C135: library part CMP-0006985-4, "CAP, CERM, 3300 pF, 50 V, +/- 10%, X7R, 0603", Cap_Case=0603, Manufacturer=Kemet, Supplier Part Number 1=399-5339-1-ND, TempCo=X7R, Tolerance_%=10%, Value1=Unknown, Value2=50V, ValueDisplayed=3300pF
C136 C149 C152 C261: library part CMP-0006659-2, "CAP, CERM, 0.1 uF, 25 V, +/- 10%, X7R, 0402", Cap_Case=0402, Manufacturer=MuRata, Supplier Part Number 1=490-10698-1-ND, TempCo=X7R, Tolerance_%=10%, Value1=Unknown, Value2=25V, ValueDisplayed=0.1uF
C137: library part CMP-0007255-4, "CAP, CERM, 22 pF, 100 V, +/- 5%, C0G/NP0, 0603", Cap_Case=0603, Manufacturer=MuRata, Supplier Part Number 1=490-1335-1-ND, TempCo=C0G/NP0, Tolerance_%=5%, Value1=Unknown, Value2=100V, ValueDisplayed=22pF
C139 C140: library part CMP-0009220-2, "CAP, CERM, 47 uF, 10 V, +/- 10%, X7R, 1210", Cap_Case=1210, Manufacturer=MuRata, Supplier Part Number 1=490-5312-1-ND, TempCo=X7R, Tolerance_%=10%, Value1=Unknown, Value2=10V, ValueDisplayed=47uF
C141: library part CMP-0085283-1, "CAP, CERM, 10 µF, 16 V,+/- 10%, X7R, 0805", Cap_Case=0805, Manufacturer="Taiyo Yuden", TempCo=X7R, Tolerance_%=10%, Value2=16V, ValueDisplayed=10µF
C146: library part CMP-0006853-4, "CAP, CERM, 0.01 uF, 16 V, +/- 10%, X7R, 0603", Cap_Case=0603, Manufacturer=Kemet, Supplier Part Number 1=399-7841-1-ND, TempCo=X7R, Tolerance_%=10%, Value1=Unknown, Value2=16V, ValueDisplayed=0.01uF
C147 C150 C154: library part CMP-0079154-1, "CAP, CERM, 1 µF, 16 V,+/- 10%, X7R, AEC-Q200 Grade 1, 0603", Cap_Case=0603, Manufacturer=MuRata, Supplier Part Number 1=490-12657-1-ND, TempCo=X7R, Tolerance_%=10%, Value2=16V, ValueDisplayed=1µF
C148 C153: library part CMP-0006674-2, "CAP, CERM, 0.01 uF, 50 V, +/- 10%, X7R, 0402", Cap_Case=0402, Manufacturer=MuRata, Supplier Part Number 1=490-4516-1-ND, TempCo=X7R, Tolerance_%=10%, Value1=Unknown, Value2=50V, ValueDisplayed=0.01uF
C156 C158: library part CMP-0006251-2, "CAP, CERM, 68 pF, 50 V, +/- 5%, C0G/NP0, 0402", Cap_Case=0402, Manufacturer=TDK, Supplier Part Number 1=445-1245-1-ND, TempCo=C0G/NP0, Tolerance_%=5%, Value1=Unknown, Value2=50V, ValueDisplayed=68pF
C157: library part CMP-0006987-4, "CAP, CERM, 4700 pF, 50 V, +/- 10%, X7R, 0603", Cap_Case=0603, Manufacturer=Kemet, Supplier Part Number 1=399-5337-1-ND, TempCo=X7R, Tolerance_%=10%, Value1=Unknown, Value2=50V, ValueDisplayed=4700pF
C192_L1 C192_L2 C192_L3 C192_N C208_L1 C208_L2 C208_L3 C208_N C232_L1 C232_L2 C232_L3 C232_N C249_L1 C249_L2 C249_L3 C249_N: library part CMP-0009015-2, "CAP, CERM, 10 uF, 50 V, +/- 10%, X5R, AEC-Q200 Grade 1, 1206", Cap_Case=1206, Manufacturer=MuRata, Supplier Part Number 1=490-12456-1-ND, TempCo=X5R, Tolerance_%=10%, Value1=Unknown, Value2=50V, ValueDisplayed=10uF
C193_L1 C193_L2 C193_L3 C193_N C210_L1 C210_L2 C210_L3 C210_N C233_L1 C233_L2 C233_L3 C233_N C250_L1 C250_L2 C250_L3 C250_N: library part CMP-0119293-1, "WCAP-CSGP Multilayer Ceramic Chip Capacitor, General Purpose, size 0402, X7R, 2.2nF, 50VDC", Capacitance Tolerance=+/-10%, Case/Size Code=0402, Insulation Resistance=10GOhm, Manufacturer="Wurth Elektronik", Operating Temperature Max=125°C, Operating Temperature Min=-55°C, Rated Voltage (DC)=50V
C199_L1 C199_L2 C199_L3 C199_N C222_L1 C222_L2 C222_L3 C222_N C239_L1 C239_L2 C239_L3 C239_N C256_L1 C256_L2 C256_L3 C256_N: library part CMP-0115362-1, "WCAP-CSGP Multilayer Ceramic Chip Capacitor, General Purpose, size 0402, X7R, 15nF, 25VDC", Capacitance Tolerance=+/-10%, Case/Size Code=0402, Insulation Resistance=10GOhm, Manufacturer="Wurth Elektronik", Operating Temperature Max=125°C, Operating Temperature Min=-55°C, Rated Voltage (DC)=25V
C213_L1 C213_L2 C213_L3 C213_N: library part CMP-0124359-1, "Cap Film 12uF 630V PP 10% (42 X 28 X 42.5mm) Radial 0.0055 Ohm 100°C Bulk", Digikey Part Number=495-B32676G6126K000-ND, Manufacturer=TDK, Mouser Part Number=871-B32676G6126K, Operating Temperature Range="-40°C to +105°C", Tolerance_%=10%, ValueDisplayed=12uF
C215_L1 C215_L2 C215_L3 C215_N: library part CMP-0009326-2, "CAP, CERM, 0.1 uF, 1000 V, +/- 10%, X7R, 1812", Cap_Case=1812, Manufacturer=Kemet, Supplier Part Number 1=399-6523-1-ND, TempCo=X7R, Tolerance_%=10%, Value1=Unknown, Value2=1000V, ValueDisplayed=0.1uF
C216_L1 C216_L2 C216_L3 C216_N C217_L1 C217_L2 C217_L3 C217_N: library part CMP-0009331-2, "CAP, CERM, 0.1 uF, 1500 V, +/- 10%, X7R, 2225", Cap_Case=2225, Manufacturer=Kemet, Supplier Part Number 1=399-10501-1-ND, TempCo=X7R, Tolerance_%=10%, Value1=Unknown, Value2=1500V, ValueDisplayed=0.1uF
D1 D2: library part CMP-0093310-1, "Standard LEDs - SMD Green TOPLED E 1608", Color=Green, Forward Current=2mA, Manufacturer="Osram Opto", Mouser Part Number=720-KGDELLS122A4849, Operating Temperature Range="-40°C to +110°C"
D3 D17: library part CMP-0028389-2, "Diode, Schottky, 60 V, 1 A, SMA", Manufacturer="Diodes Inc.", Value1=1A, Value2=0.7V
D4 D6 D18: library part CMP-0002894-2, "LED, Green, SMD", Color=green, Manufacturer="Wurth Elektronik", Value1=W, Value2=2V
D5: library part CMP-0028350-2, "Diode, Schottky, 30 V, 3 A, SMA", Manufacturer="Diodes Inc.", Value1=3A, Value2=0.5V
D7_L1 D7_L2 D7_L3 D7_N D8_L1 D8_L2 D8_L3 D8_N D9_L1 D9_L2 D9_L3 D9_N D13_L1 D13_L2 D13_L3 D13_N D14_L1 D14_L2 D14_L3 D14_N D15_L1 D15_L2 D15_L3 D15_N: library part CMP-0122312-1, "Zener Diode 180 V 1 W ±5% Surface Mount DO-213AB (GL41)", Digikey Part Number=ZGL41-180A-E3/96GICT-ND, Manufacturer=Vishay, Max Reverse Leakage Current=1uA, Mouser Part Number=625-ZGL41-180A-E3, Operating Temperature Range="-55°C to +150°C", Power_W=1000mW
D10_L1 D10_L2 D10_L3 D10_N D11_L1 D11_L2 D11_L3 D11_N D12_L1 D12_L2 D12_L3 D12_N D16_L1 D16_L2 D16_L3 D16_N: library part CMP-0091305-2, "Red 630nm LED Indication - Discrete 2V 0603 (1608 Metric)", Color=Red, Digikey Part Number=754-1359-1-ND, Forward Current=20mA, Manufacturer=Kingbright, Mouser Part Number=604-APG1608SURKC/T, Operating Temperature Range="-40°C to +85°C", Power_TotalModule=75mW
F1 F2 F3 F4: library part CMP-0122960-1, "25 A 250 V AC 80 V DC Fuse Board Mount (Cartridge Style Excluded) Surface Mount 2-SMD, Square End Block", Digikey Part Number=SF-3812F2500T-2CT-ND, Fuse Current=25A, Fuse Interrupt Dc Current=130A, Manufacturer=Bourns, Mouser Part Number=652-SF-3812F2500T-2, Operating Temperature Range="-55°C to +125°C"
FB1 FB2 FB3 FB4 FB5 FB6 FB7 FB8 FB9 FB10 FB11 FB14_L1 FB14_L2 FB14_L3 FB14_N FB15_L1 FB15_L2 FB15_L3 FB15_N FB16: library part CMP-0037505-1, "600 Ohms @ 100 MHz 1 Power, Signal Line Ferrite Bead 0603 (1608 Metric) 1A 200mOhm", Digikey Part Number=MH1608-601YCT-ND, Impedance At Frequency="600Ω @ 100MHz", Manufacturer=Bourns, Mouser Part Number=652-MH1608-601Y, Operating Temperature Range="-55°C to +125°C", Test Frequency=100MHz, Tolerance_%=25%
FB12 FB13 FB17 FB18: library part CMP-0041881-1, "Chip Ferrite Bead, 0402, 330Ω @ 100MHz, 0.205Ω, 25%, 1.1A", Impedance At Frequency="330Ω @ 100MHz", Manufacturer=Murata, Operating Temperature Range="-55°C to +125°C", Test Frequency=100MHz, Tolerance_%=25%
FID1 FID2 FID3: library part CMP-0077181-1, "Fiducial mark.  There is nothing to buy or mount.", Manufacturer=N/A
J1: library part CMP-0054820-2, "Receptacle, D-Sub, 9 Position, R/A, TH", Color=Black, Current_A=3A, Manufacturer="Wurth Elektronik", Supplier Part Number 1=16T0655, Voltage_V=125V
J2: library part CMP-0055799-1, "Panel Socket, 24A, R/A, Gold, TH", Color=Red, Current_A=24A, Manufacturer="Cliff Electronic Components", Supplier Part Number 1=20T2058, Voltage_V=1kV
J3 J5 J7: library part CMP-0098296-2, "Banana Test Connector, Socket, PCB Mount, 24 A, 1 kV, Gold Plated Contacts, Brown", Current_A=24A, Digikey Part Number=4654-FCR7350N-ND, Manufacturer="CLIFF Electronic Components", Operating Temperature Range="-40°C to +80°C", Voltage_V=1kV
J4 J6 J21: library part CMP-0122568-1, "Mini-Latch™ Wire-to-Board Header, Vertical, with Friction Ramp, 3 Circuits, Gold (Au) Plating", Current_A=3A, Digikey Part Number=23-0022111031-ND, Manufacturer=Molex, Mouser Part Number=538-22-11-1031, Operating Temperature Range="-40°C to +105°C", Voltage_V=250V
J8 J9: library part CMP-0055798-1, "Panel Socket, 24A, R/A, Gold, TH", Color=Black, Current_A=24A, Manufacturer="Cliff Electronic Components", Supplier Part Number 1=20T2055, Voltage_V=1kV
J10: library part CMP-0098294-2, "Banana Test Connector, Socket, PCB Mount, 24 A, 1 kV, Gold Plated Contacts, Green", Current_A=24A, Digikey Part Number=4654-FCR7350G-ND, Manufacturer="CLIFF Electronic Components", Operating Temperature Range="-40°C to +80°C", Voltage_V=1kV
J11 J14 J15 J17 J18: library part CMP-0075491-1, "Header, 100mil, 2x1, Tin, SMD", Color=Black, Current_A=5.4A, Manufacturer=Samtec, Supplier Part Number 1=77P4673, Voltage_V=475V
J12: library part CMP-0003814-2, "C2000 controlCARD-120HSEC connector, SMT", Manufacturer=Samtec
J13: library part CMP-0075424-1, "Header, 100mil, 12x1, Gold, TH", Color=Black, Current_A=6.3A, Manufacturer=Samtec, Supplier Part Number 1=SAM1029-12-ND, Voltage_V=550V
J16: library part CMP-0075012-1, "Power Jack, SMT", Manufacturer="CUI Inc.", Supplier Part Number 1=CP-002AHPJDKR-ND
L1 L2 L5 L6: library part CMP-0124380-1, "Boost Inductor TIDA-010957", Manufacturer=Bourns, Operating Temperature Range="-40°C to +125°C", Test Frequency=100kHz, Tolerance_%=10%
L3: library part CMP-0084086-1, "100µH @ 100kHz 2 Line Common Mode Choke Surface Mount 5.8 kOhms @ 10MHz 150mA DCR 2Ohm", Digikey Part Number=445-3959-1-ND, Impedance At Frequency="5800Ω @ 10MHz", Manufacturer=TDK, Mouser Part Number=810-ACT45B1012PTL003, Operating Temperature Range="-40°C to +150°C", Test Frequency=100kHz, Tolerance_%=+50/-30%
L7 L8 L9 L11_L1 L11_L2 L11_L3 L11_N L13_L1 L13_L2 L13_L3 L13_N L15_L1 L15_L2 L15_L3 L15_N L17_L1 L17_L2 L17_L3 L17_N: library part CMP-0100992-1, "WE-PMI SMT Power Multilayer Inductor, size 0603, 2.2uH, 0.8A, 375mOhm", Case/Size Code=0603, DC Resistance=375mOhm, Inductance=2.2uH, Inductance Tolerance=20%, Manufacturer="Wurth Elektronik", Operating Temperature Max=125°C, Operating Temperature Min=-40°C, Rated Current=0.8A, Saturation Current=0.28A, Self Resonant Frequency=80MHz
L10_L1 L10_L2 L10_L3 L10_N L12_L1 L12_L2 L12_L3 L12_N L14_L1 L14_L2 L14_L3 L14_N L16_L1 L16_L2 L16_L3 L16_N: library part CMP-0057419-2, "Inductor, Drum Core, Ferrite, 15 uH, 0.65 A, 0.4 ohm, SMD", Manufacturer=Bourns, Supplier Part Number 1=SDR0302-150MLCT-ND, Value1="0.4 ohm", Value2=0.65A, ValueDisplayed=15uH
L12 L19: library part CMP-0124379-2, "4-Phase CMC", Manufacturer=Bourns, Operating Temperature Range="-40°C to +125°C", Test Frequency=100kHz, Tolerance_%=+50/-35%
LBL1: library part CMP-0003625-1, "Thermal Transfer Printable Labels, 0.650\" W x 0.200\" H - 10,000 per roll", Manufacturer=Brady, Supplier Part Number 1=97C5133
Logo1: library part CMP-0074844-1
Logo2: library part CMP-0074838-1, "Texas Instrument Corporate Signature"
Logo3: library part CMP-0074847-1, "FCC_disclaimer"
Logo4: library part CMP-0074769-1
MP1 MP2 MP3 MP4 MP5 MP6 MP7 MP8 MP9 MP10 MP10 MP11 MP12 MP13 MP14 MP15: library part CMP-0124333-1, "Round Spacer Unthreaded Steel 0.118\" (3.00mm)", Digikey Part Number=732-7087-1-ND, Manufacturer=Wurth, Mouser Part Number=710-9774030960R, Operating Temperature Range="-55°C to +150°C"
Q1 Q2 Q3: library part CMP-0000585-1, "MOSFET, N-CH, 30 V, 22 A, DQK0006C (WSON-6)", Alternate Manufacturer=None, Manufacturer="Texas Instruments", Supplier Part Number 1=296-37193-1-ND, Value1=0.02, Value2="2.4 nC"
R1 R2 R3 R4 R5 R6 R7 R8 R9 R10 R11 R12 R13 R14 R15 R16 R17 R18: library part CMP-0018695-3, "RES, 510 k, 5%, 0.25 W, AEC-Q200 Grade 0, 1206", Manufacturer=Vishay-Dale, Power_W=250mW, Supplier Part Number 1=541-510KECT-ND, TempCo="200 ppm/C", Tolerance_%=5%, Value2=0.25W, Value_Code=510k
R19 R25 R29 R30 R43 R44 R45 R46 R47 R48 R49 R50 R51 R52 R53 R54 R55 R56 R57 R58 R59 R60 R61 R79 R80 R146 R151 R156 R161 R165 R166 R167 R168 R176 R177 R178 R179 R180 R181 R182 R183 R195 R196 R197 R198 R293_L1 R293_L2 R293_L3 R293_N: library part CMP-0026696-1, "RES, 33.0, 1%, 0.1 W, 0402", Manufacturer=Panasonic, Power_W=100mW, Supplier Part Number 1=P33.0LCT-ND, TempCo="100 ppm/C", Tolerance_%=1%, Value2=0.1W, Value_Code=33R0, ValueDisplayed=33.0
R20 R21 R22 R23 R24 R26 R27 R28 R31 R32 R33 R34 R35 R36 R37 R38 R39 R40 R41 R42 R62 R63 R64 R65 R66 R67 R68 R69 R70 R71 R72 R73 R74 R75 R76 R77 R78 R84 R86 R88 R225 R228 R334: library part CMP-0081973-1, "RES, 0, 0%, 0.25 W, AEC-Q200 Grade 0, 0603", Manufacturer=Vishay-Dale, Power_W=250mW, Supplier Part Number 1=541-2779-1-ND, Tolerance_%=0%, Value2=0.25W, Value_Code=0
R81 R82: library part CMP-0025936-5, "RES, 680, 5%, 0.1 W, 0603", Manufacturer=Yageo, Power_W=100mW, Supplier Part Number 1=311-680GRCT-ND, TempCo="100 ppm/C", Tolerance_%=5%, Value2=0.1W, Value_Code=680R, ValueDisplayed=680
R83 R85 R87 R92: library part CMP-0097004-1, "PTCEL Series 500 V 60 Ohm ±30 % Radial Inrush Current Limiter PTC Thermistor", Digikey Part Number=BC3317-ND, Hold Current=120mA, Manufacturer="Vishay Bccomponents", Mouser Part Number=594-PTCEL13R600LBE, Operating Temperature Range="-40°C to +105°C", Tolerance_%=30%
R89 R90 R91 R94: library part CMP-0096768-1, "5 kA Varistor 1 Circuit Through Hole Disc 17mm", Clamping Voltage=730V, Digikey Part Number=118-ISOM5-275-B-L2-ND, Manufacturer=Bourns, Mouser Part Number=652-ISOM5-275-B-L2, Operating Temperature Range="-40°C to +125°C", ValueDisplayed=40pF
R93 R217: library part CMP-0082532-1, "RES, 499, 1%, 0.1 W, 0603", Manufacturer=Vishay-Dale, Power_W=100mW, Supplier Part Number 1=541-3986-1-ND, TempCo="100 ppm/C", Tolerance_%=1%, Value2=0.1W, Value_Code=499R, ValueDisplayed=499
R96 R130 R131 R132 R133 R134 R135: library part CMP-0026656-1, "RES, 100, 1%, 0.1 W, 0402", Manufacturer=Panasonic, Power_W=100mW, Supplier Part Number 1=P100LCT-ND, TempCo="100 ppm/C", Tolerance_%=1%, Value2=0.1W, Value_Code=100R, ValueDisplayed=100
R97 R99 R105 R109 R113 R117 R121 R123 R129 R284_L1 R284_L2 R284_L3 R284_N R287_L1 R287_L2 R287_L3 R287_N R295_L1 R295_L2 R295_L3 R295_N R298_L1 R298_L2 R298_L3 R298_N R305_L1 R305_L2 R305_L3 R305_N R308_L1 R308_L2 R308_L3 R308_N R322_L1 R322_L2 R322_L3 R322_N R325_L1 R325_L2 R325_L3 R325_N: library part CMP-0021998-4, "RES, 10.0 k, 1%, 0.1 W, AEC-Q200 Grade 0, 0603", Manufacturer=Vishay-Dale, Power_W=100mW, Supplier Part Number 1=541-10.0KHCT-ND, TempCo="100 ppm/C", Tolerance_%=1%, Value2=0.1W, Value_Code=10k0, ValueDisplayed=10.0k
R98 R100 R102 R103 R106 R107 R110 R111 R114 R115 R118 R119 R122 R124 R126 R127 R139 R141 R145 R147 R150 R152 R155 R157 R160 R162 R331 R333: library part CMP-0077124-1, "RES, 10.0 k, 0.1%, 0.1 W, AEC-Q200 Grade 0, 0402", Manufacturer=Vishay/Beyschlag, Power_W=100mW, Supplier Part Number 1=MCS0402-10.0K-MBCT-ND, TempCo="25 ppm/C", Tolerance_%=0.1%, Value2=0.1W, Value_Code=10k0, ValueDisplayed=10.0k
R101 R108 R116 R125 R140: library part CMP-0026283-2, "RES, 309, 1%, 0.063 W, AEC-Q200 Grade 0, 0402", Manufacturer=Vishay-Dale, Power_W=63mW, Supplier Part Number 1=541-309LCT-ND, TempCo="100 ppm/C", Tolerance_%=1%, Value2=0.063W, Value_Code=309R, ValueDisplayed=309
R104 R112 R120 R128: library part CMP-0023112-5, "RES, 43.2 k, 1%, 0.1 W, 0603", Manufacturer=Yageo, Power_W=100mW, Supplier Part Number 1=311-43.2KHRCT-ND, TempCo="100 ppm/C", Tolerance_%=1%, Value2=0.1W, Value_Code=43k2, ValueDisplayed=43.2k
R136 R143: library part CMP-0078244-2, "RES, 30.0 k, 1%, 0.063 W, AEC-Q200 Grade 0, 0402", Manufacturer=Vishay-Dale, Power_W=63mW, Supplier Part Number 1=541-30.0KLCT-ND, TempCo="100 ppm/C", Tolerance_%=1%, Value2=0.063W, Value_Code=30k0, ValueDisplayed=30.0k
R137 R142: library part CMP-0065359-1, "RES, 15.0 k, .1%, .063 W, AEC-Q200 Grade 0, 0402", Manufacturer=Panasonic, Power_W=63mW, Supplier Part Number 1=P15KDCCT-ND, TempCo="25 ppm/C", Tolerance_%=0.1%, Value1=.1%, Value2=.063W, Value_Code=15k0, ValueDisplayed=15.0k
R138: library part CMP-0027004-2, "RES, 0, 5%, 0.063 W, 0402", Manufacturer="Yageo America", Power_W=63mW, Supplier Part Number 1=311-0.0JRCT-ND, TempCo="200 ppm/C", Tolerance_%=5%, Value2=0.063W, Value_Code=0000, ValueDisplayed=0
R144 R148 R149 R153 R154 R158 R159 R163: library part CMP-0023778-2, "RES, 15.6 k, 0.1%, 0.1 W, 0603", Manufacturer="Yageo America", Power_W=100mW, TempCo="25 ppm/C", Tolerance_%=0.1%, Value2=0.1W, Value_Code=15k6, ValueDisplayed=15.6k
R164 R174 R175 R194 R332: library part CMP-0026827-3, "RES, 10, 5%, 0.063 W, AEC-Q200 Grade 0, 0402", Manufacturer=Vishay-Dale, Power_W=63mW, Supplier Part Number 1=541-10JCT-ND, TempCo="200 ppm/C", Tolerance_%=5%, Value2=0.063W, Value_Code=10R0, ValueDisplayed=10
R169 R170 R171 R172 R173 R184 R185 R186 R187 R188 R189 R190 R191 R192 R193 R199 R200 R201 R202 R203 R224 R330: library part CMP-0025958-3, "RES, 10.0 k, 1%, 0.063 W, AEC-Q200 Grade 0, 0402", Manufacturer=Vishay-Dale, Power_W=63mW, Supplier Part Number 1=541-10.0KLCT-ND, TempCo="100 ppm/C", Tolerance_%=1%, Value2=0.063W, Value_Code=10k0, ValueDisplayed=10.0k
R204: library part CMP-0023128-4, "RES, 470 k, 1%, 0.1 W, 0603", Manufacturer=Yageo, Power_W=100mW, Supplier Part Number 1=311-470KHRCT-ND, TempCo="100 ppm/C", Tolerance_%=1%, Value2=0.1W, Value_Code=470k
R205 R209 R211 R219: library part CMP-0023133-5, "RES, 47.0 k, 1%, 0.1 W, 0603", Manufacturer=Yageo, Power_W=100mW, Supplier Part Number 1=311-47.0KHRCT-ND, TempCo="100 ppm/C", Tolerance_%=1%, Value2=0.1W, Value_Code=47k0, ValueDisplayed=47.0k
R206: library part CMP-0022870-5, "RES, 1.10 k, 1%, 0.1 W, 0603", Manufacturer=Yageo, Power_W=100mW, Supplier Part Number 1=311-1.10KHRCT-ND, TempCo="100 ppm/C", Tolerance_%=1%, Value2=0.1W, Value_Code=1k10, ValueDisplayed=1.10k
R207: library part CMP-0023203-5, "RES, 5.60 k, 1%, 0.1 W, 0603", Manufacturer=Yageo, Power_W=100mW, Supplier Part Number 1=311-5.60KHRCT-ND, TempCo="100 ppm/C", Tolerance_%=1%, Value2=0.1W, Value_Code=5k60, ValueDisplayed=5.60k
R208: library part CMP-0022763-5, "RES, 11.0 k, 1%, 0.1 W, 0603", Manufacturer=Yageo, Power_W=100mW, Supplier Part Number 1=311-11.0KHRCT-ND, TempCo="100 ppm/C", Tolerance_%=1%, Value2=0.1W, Value_Code=11k0, ValueDisplayed=11.0k
R210: library part CMP-0023000-5, "RES, 2.00 k, 1%, 0.1 W, 0603", Manufacturer=Yageo, Power_W=100mW, Supplier Part Number 1=311-2.00KHRCT-ND, TempCo="100 ppm/C", Tolerance_%=1%, Value2=0.1W, Value_Code=2k00, ValueDisplayed=2.00k
R212: library part CMP-0022816-5, "RES, 15.0 k, 1%, 0.1 W, 0603", Manufacturer=Yageo, Power_W=100mW, Supplier Part Number 1=311-15.0KHRCT-ND, TempCo="100 ppm/C", Tolerance_%=1%, Value2=0.1W, Value_Code=15k0, ValueDisplayed=15.0k
R213: library part CMP-0023180-5, "RES, 54.9 k, 1%, 0.1 W, 0603", Manufacturer=Yageo, Power_W=100mW, Supplier Part Number 1=311-54.9KHRCT-ND, TempCo="100 ppm/C", Tolerance_%=1%, Value2=0.1W, Value_Code=54k9, ValueDisplayed=54.9k
R214: library part CMP-0022917-4, "RES, 220 k, 1%, 0.1 W, 0603", Manufacturer=Yageo, Power_W=100mW, Supplier Part Number 1=311-220KHRCT-ND, TempCo="100 ppm/C", Tolerance_%=1%, Value2=0.1W, Value_Code=220k
R215 R218: library part CMP-0023020-5, "RES, 30.0 k, 1%, 0.1 W, 0603", Manufacturer=Yageo, Power_W=100mW, Supplier Part Number 1=311-30.0KHRCT-ND, TempCo="100 ppm/C", Tolerance_%=1%, Value2=0.1W, Value_Code=30k0, ValueDisplayed=30.0k
R216: library part CMP-0023404-3, "RES, 10.0 k, 0.1%, 0.1 W, 0603", Manufacturer="Susumu Co Ltd", Power_W=100mW, Supplier Part Number 1=RG16P10.0KBCT-ND, TempCo="25 ppm/C", Tolerance_%=0.1%, Value2=0.1W, Value_Code=10k0, ValueDisplayed=10.0k
R220 R221 R222 R223: library part CMP-0124381-1, "Power Relay 12VDC 25A SPST-NO(30.1x15.7x23.3)mm THT", Coil Power_W=780mW, Coil Resistance=185Ω, Coil Voltage_VDC=12V, Contact Rating_A=25A, Manufacturer="FCL Components", Mouser Part Number=817-FTR-K3AB012W-WG, Operating Temperature Range="-40°C to +85°C"
R226 R227: library part CMP-0025431-3, "RES, 59.7, 0.5%, 0.1 W, 0603", Manufacturer="Yageo America", Power_W=100mW, TempCo="50 ppm/C", Tolerance_%=0.5%, Value2=0.1W, Value_Code=59R7, ValueDisplayed=59.7
R278_L1 R278_L2 R278_L3 R278_N R279_L1 R279_L2 R279_L3 R279_N R291_L1 R291_L2 R291_L3 R291_N R292_L1 R292_L2 R292_L3 R292_N R302_L1 R302_L2 R302_L3 R302_N R303_L1 R303_L2 R303_L3 R303_N R316_L1 R316_L2 R316_L3 R316_N R317_L1 R317_L2 R317_L3 R317_N: library part CMP-0025787-4, "RES, 33, 5%, 0.1 W, AEC-Q200 Grade 0, 0603", Manufacturer=Vishay-Dale, Power_W=100mW, Supplier Part Number 1=541-33GCT-ND, TempCo="200 ppm/C", Tolerance_%=5%, Value2=0.1W, Value_Code=33R0, ValueDisplayed=33
R281_L1 R281_L2 R281_L3 R281_N R282_L1 R282_L2 R282_L3 R282_N R319_L1 R319_L2 R319_L3 R319_N R320_L1 R320_L2 R320_L3 R320_N: library part CMP-0016570-3, "RES, 100, 1%, 0.5 W, AEC-Q200 Grade 0, 1206", Manufacturer=Vishay-Dale, Power_W=500mW, Supplier Part Number 1=541-100UCT-ND, TempCo="100 ppm/C", Tolerance_%=1%, Value2=0.5W, Value_Code=100R, ValueDisplayed=100
R283_L1 R283_L2 R283_L3 R283_N R294_L1 R294_L2 R294_L3 R294_N R304_L1 R304_L2 R304_L3 R304_N R321_L1 R321_L2 R321_L3 R321_N: library part CMP-0025828-4, "RES, 56 k, 5%, 0.1 W, AEC-Q200 Grade 0, 0603", Manufacturer=Vishay-Dale, Power_W=100mW, Supplier Part Number 1=541-56KGCT-ND, TempCo="200 ppm/C", Tolerance_%=5%, Value2=0.1W, Value_Code=56k0, ValueDisplayed=56k
R285_L1 R285_L2 R285_L3 R285_N R296_L1 R296_L2 R296_L3 R296_N R306_L1 R306_L2 R306_L3 R306_N R323_L1 R323_L2 R323_L3 R323_N: library part CMP-0022746-5, "RES, 10.0 k, 1%, 0.1 W, 0603", Manufacturer=Yageo, Power_W=100mW, Supplier Part Number 1=311-10.0KHRCT-ND, TempCo="100 ppm/C", Tolerance_%=1%, Value2=0.1W, Value_Code=10k0, ValueDisplayed=10.0k
R286_L1 R286_L2 R286_L3 R286_N R297_L1 R297_L2 R297_L3 R297_N R307_L1 R307_L2 R307_L3 R307_N R324_L1 R324_L2 R324_L3 R324_N: library part CMP-0022961-4, "RES, 270 k, 1%, 0.1 W, 0603", Manufacturer=Yageo, Power_W=100mW, Supplier Part Number 1=311-270KHRCT-ND, TempCo="100 ppm/C", Tolerance_%=1%, Value2=0.1W, Value_Code=270k
R288_L1 R288_L2 R288_L3 R288_N R299_L1 R299_L2 R299_L3 R299_N R309_L1 R309_L2 R309_L3 R309_N R326_L1 R326_L2 R326_L3 R326_N: library part CMP-0022735-5, "RES, 100 k, 1%, 0.1 W, 0603", Manufacturer=Yageo, Power_W=100mW, Supplier Part Number 1=311-100KHRCT-ND, TempCo="100 ppm/C", Tolerance_%=1%, Value2=0.1W, Value_Code=100k
R289_L1 R289_L2 R289_L3 R289_N R300_L1 R300_L2 R300_L3 R300_N R310_L1 R310_L2 R310_L3 R310_N R327_L1 R327_L2 R327_L3 R327_N: library part CMP-0023289-4, "RES, 825 k, 1%, 0.1 W, 0603", Manufacturer=Yageo, Power_W=100mW, Supplier Part Number 1=311-825KHRCT-ND, TempCo="100 ppm/C", Tolerance_%=1%, Value2=0.1W, Value_Code=825k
